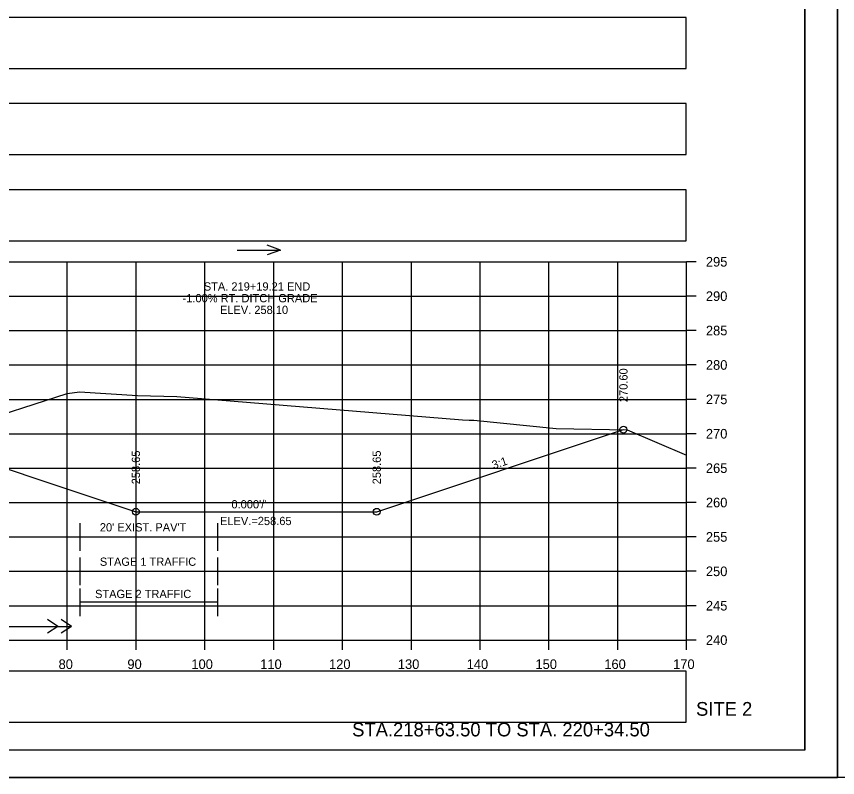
# Model space of a CAD drawing. Extents: x 4667 to 1632277, y -2100 to 724501.
# Drawn here: x 5849.8 to 5969.1, y -897.1 to -786.4 of the extents above; entities that cross this region are included whole.
import ezdxf

# ---------------------------------------------------------------- set-up
doc = ezdxf.new("R2010")
doc.units = 0
for name, color, linetype in [('R_Axis', 7, 'Continuous'), ('R_Axis Annot', 7, 'Continuous'), ('R_Border', 7, 'Continuous'), ('R_Draft', 7, 'Continuous'), ('R_Exist Surface', 7, 'Continuous'), ('R_Fin Surface', 7, 'Continuous'), ('R_Fin Surface Annot', 7, 'Continuous'), ('R_Grid', 7, 'Continuous'), ('R_No Plot', 7, 'Continuous'), ('R_Proposed CofA', 7, 'Continuous'), ('R_Temp Easement', 7, 'Continuous'), ('R_Water Annot', 7, 'Continuous')]:
    doc.layers.add(name, color=color, linetype=linetype)

msp = doc.modelspace()

# ---------------------------------------------------------------- linework, layer by layer
at = {"layer": 'R_Axis'}
for p, q in [((5947.18, -877.09), (5947.18, -822.09)), ((5948.58, -822.09), (5947.18, -822.09)), ((5948.58, -827.09), (5947.18, -827.09)), ((5948.58, -832.09), (5947.18, -832.09)), ((5948.58, -837.09), (5947.18, -837.09)), ((5948.58, -842.09), (5947.18, -842.09)), ((5948.58, -847.09), (5947.18, -847.09)), ((5948.58, -852.09), (5947.18, -852.09)), ((5948.58, -857.09), (5947.18, -857.09)), ((5948.58, -862.09), (5947.18, -862.09)), ((5948.58, -867.09), (5947.18, -867.09)), ((5948.58, -872.09), (5947.18, -872.09)), ((5667.18, -877.09), (5947.18, -877.09)), ((5857.18, -878.49), (5857.18, -877.09)), ((5867.18, -878.49), (5867.18, -877.09)), ((5877.18, -878.49), (5877.18, -877.09)), ((5887.18, -878.49), (5887.18, -877.09)), ((5897.18, -878.49), (5897.18, -877.09)), ((5907.18, -878.49), (5907.18, -877.09)), ((5917.18, -878.49), (5917.18, -877.09)), ((5927.18, -878.49), (5927.18, -877.09)), ((5937.18, -878.49), (5937.18, -877.09)), ((5947.18, -878.49), (5947.18, -877.09)), ((5948.58, -877.09), (5947.18, -877.09))]:
    msp.add_line(p, q, dxfattribs=at)
at = {"layer": 'R_Border'}
for q in [(5964.36, -687.63), (5648.18, -893.09)]:
    msp.add_line((5964.36, -893.09), q, dxfattribs=at)
at = {"layer": 'R_Exist Surface'}
msp.add_lwpolyline([(5847.56, -844.33), (5857.17, -841.24), (5858.94, -841), (5867.39, -841.54), (5873.09, -841.68), (5880.85, -842.3), (5914.63, -845.08), (5915.6, -845.1), (5916.28, -845.13), (5928.22, -846.31), (5938.53, -846.5), (5947.18, -850.22)], dxfattribs=at)
at = {"layer": 'R_Fin Surface'}
for points in [[(5721.26, -843.92), (5728.56, -846.36), (5753.88, -837.92), (5757.47, -836.72), (5757.68, -836.67), (5759.68, -836.58), (5767.18, -836.25), (5777.18, -835.81), (5787.18, -835.37), (5794.68, -835.04), (5796.68, -834.95), (5802.09, -836.75), (5867.15, -858.44), (5877.76, -858.44), (5899.71, -858.44), (5900.51, -858.44), (5902.15, -858.44)], [(5902.15, -858.44), (5938, -846.49)]]:
    msp.add_lwpolyline(points, dxfattribs=at)
at = {"layer": 'R_Grid'}
for p, q in [((5667.18, -822.09), (5947.18, -822.09)), ((5857.18, -877.09), (5857.18, -822.09)), ((5867.18, -877.09), (5867.18, -822.09)), ((5877.18, -877.09), (5877.18, -822.09)), ((5887.18, -877.09), (5887.18, -822.09)), ((5897.18, -877.09), (5897.18, -822.09)), ((5907.18, -877.09), (5907.18, -822.09)), ((5917.18, -877.09), (5917.18, -822.09)), ((5927.18, -877.09), (5927.18, -822.09)), ((5937.18, -877.09), (5937.18, -822.09)), ((5947.18, -877.09), (5947.18, -822.09)), ((5667.18, -827.09), (5947.18, -827.09)), ((5667.18, -832.09), (5947.18, -832.09)), ((5667.18, -837.09), (5947.18, -837.09)), ((5667.18, -842.09), (5947.18, -842.09)), ((5667.18, -847.09), (5947.18, -847.09)), ((5667.18, -852.09), (5947.18, -852.09)), ((5667.18, -857.09), (5947.18, -857.09)), ((5667.18, -862.09), (5947.18, -862.09)), ((5667.18, -867.09), (5947.18, -867.09)), ((5667.18, -872.09), (5947.18, -872.09)), ((5667.18, -877.09), (5947.18, -877.09))]:
    msp.add_line(p, q, dxfattribs=at)
at = {"layer": 'R_No Plot'}
msp.add_line((5635.78, -897.07), (5969.12, -897.07), dxfattribs=at)
for points in [[(5635.78, -683.74), (5969.12, -683.74), (5969.12, -897.08), (5635.78, -897.08)], [(5969.12, -683.74), (6302.46, -683.74), (6302.46, -897.08), (5969.12, -897.08)], [(5882.1, -687.63), (5901.72, -687.63), (5901.72, -697.51), (5917.84, -697.51), (5941.04, -697.51), (5941.04, -721.84), (5964.36, -721.84), (5964.36, -893.09), (5648.18, -893.09), (5648.18, -687.63)]]:
    msp.add_lwpolyline(points, close=True, dxfattribs=at)
for centre in [(5938, -846.49), (5867.15, -858.44), (5902.15, -858.44)]:
    msp.add_circle(centre, 0.5, dxfattribs=at)
at = {"layer": 'R_Proposed CofA'}
for p, q in [((5855.82, -875.09), (5854.32, -874.09)), ((5857.82, -875.09), (5856.32, -874.09)), ((5855.82, -875.09), (5854.32, -876.09)), ((5857.82, -875.09), (5856.32, -876.09))]:
    msp.add_line(p, q, dxfattribs=at)
for points in [[(5667.23, -793.99), (5947.13, -793.99), (5947.13, -786.57), (5667.23, -786.57)], [(5667.23, -806.51), (5947.13, -806.51), (5947.13, -799.09), (5667.23, -799.09)], [(5667.23, -819.04), (5947.13, -819.04), (5947.13, -811.62), (5667.23, -811.62)], [(5667.23, -889.04), (5947.13, -889.04), (5947.13, -881.62), (5667.23, -881.62)]]:
    msp.add_lwpolyline(points, close=True, dxfattribs=at)
at = {"layer": 'R_Temp Easement'}
for p, q in [((5859.05, -864.09), (5859.05, -860.09)), ((5879.05, -864.09), (5879.05, -860.09)), ((5859.05, -862.09), (5879.05, -862.09)), ((5859.05, -869.09), (5859.05, -865.09)), ((5879.05, -869.09), (5879.05, -865.09)), ((5859.05, -867.09), (5879.05, -867.09)), ((5859.05, -873.59), (5859.05, -869.59)), ((5879.05, -873.59), (5879.05, -869.59)), ((5879.05, -871.59), (5859.05, -871.59)), ((5827.82, -875.09), (5857.82, -875.09))]:
    msp.add_line(p, q, dxfattribs=at)
at = {"layer": 'R_Water Annot'}
for p, q in [((5888.15, -820.4), (5886.23, -819.7)), ((5881.87, -820.4), (5888.15, -820.4)), ((5888.15, -820.4), (5886.23, -821.1))]:
    msp.add_line(p, q, dxfattribs=at)

# ---------------------------------------------------------------- texts
at = {"layer": 'R_Axis Annot'}
for s, p in [('295', (5949.98, -822.79)), ('290', (5949.98, -827.79)), ('285', (5949.98, -832.79)), ('280', (5949.98, -837.79)), ('275', (5949.98, -842.79)), ('270', (5949.98, -847.79)), ('265', (5949.98, -852.79)), ('260', (5949.98, -857.79)), ('255', (5949.98, -862.79)), ('250', (5949.98, -867.79)), ('245', (5949.98, -872.79)), ('240', (5949.98, -877.79)), ('80', (5855.92, -881.29)), ('90', (5865.92, -881.29)), ('100', (5875.22, -881.29)), ('110', (5885.22, -881.29)), ('120', (5895.22, -881.29)), ('130', (5905.22, -881.29)), ('140', (5915.22, -881.29)), ('150', (5925.22, -881.29)), ('160', (5935.22, -881.29)), ('170', (5945.22, -881.29))]:
    msp.add_text(s, height=1.4, dxfattribs=at).set_placement(p)
at = {"layer": 'R_Draft'}
for s, p in [('SITE 2', (5948.55, -888.09)), ('STA.218+63.50 TO STA. 220+34.50', (5898.58, -891.09))]:
    msp.add_text(s, height=2, dxfattribs=at).set_placement(p)
at = {"layer": 'R_Fin Surface Annot'}
for s, rotation, p in [('270.60', 90, (5938.6, -842.49)), ('258.65', 90, (5867.75, -854.44)), ('258.65', 90, (5902.75, -854.44)), ('3:1', 18.4349, (5919.13, -852.25))]:
    msp.add_text(s, height=1.2, rotation=rotation, dxfattribs=at).set_placement(p)
msp.add_text("0.000'/'", height=1.2, dxfattribs=at).set_placement((5881.04, -857.94))
at = {"layer": 'R_Temp Easement'}
for s, height, p in [("20' EXIST. PAV'T", 1.2, (5861.92, -861.29)), ('STAGE 1 TRAFFIC', 1.2, (5861.92, -866.29)), ('STAGE 2 TRAFFIC', 1.1985, (5861.22, -870.98))]:
    msp.add_text(s, height=height, dxfattribs=at).set_placement(p)
at = {"layer": 'R_Water Annot'}
for s, p in [('STA. 219+19.21 END', (5877.02, -826.28)), ('-1.00% RT. DITCH GRADE', (5873.94, -827.98)), ('ELEV. 258.10', (5879.37, -829.68)), ('ELEV.=258.65', (5879.38, -860.37))]:
    msp.add_text(s, height=1.2, dxfattribs=at).set_placement(p)

doc.saveas('drawing.dxf')
